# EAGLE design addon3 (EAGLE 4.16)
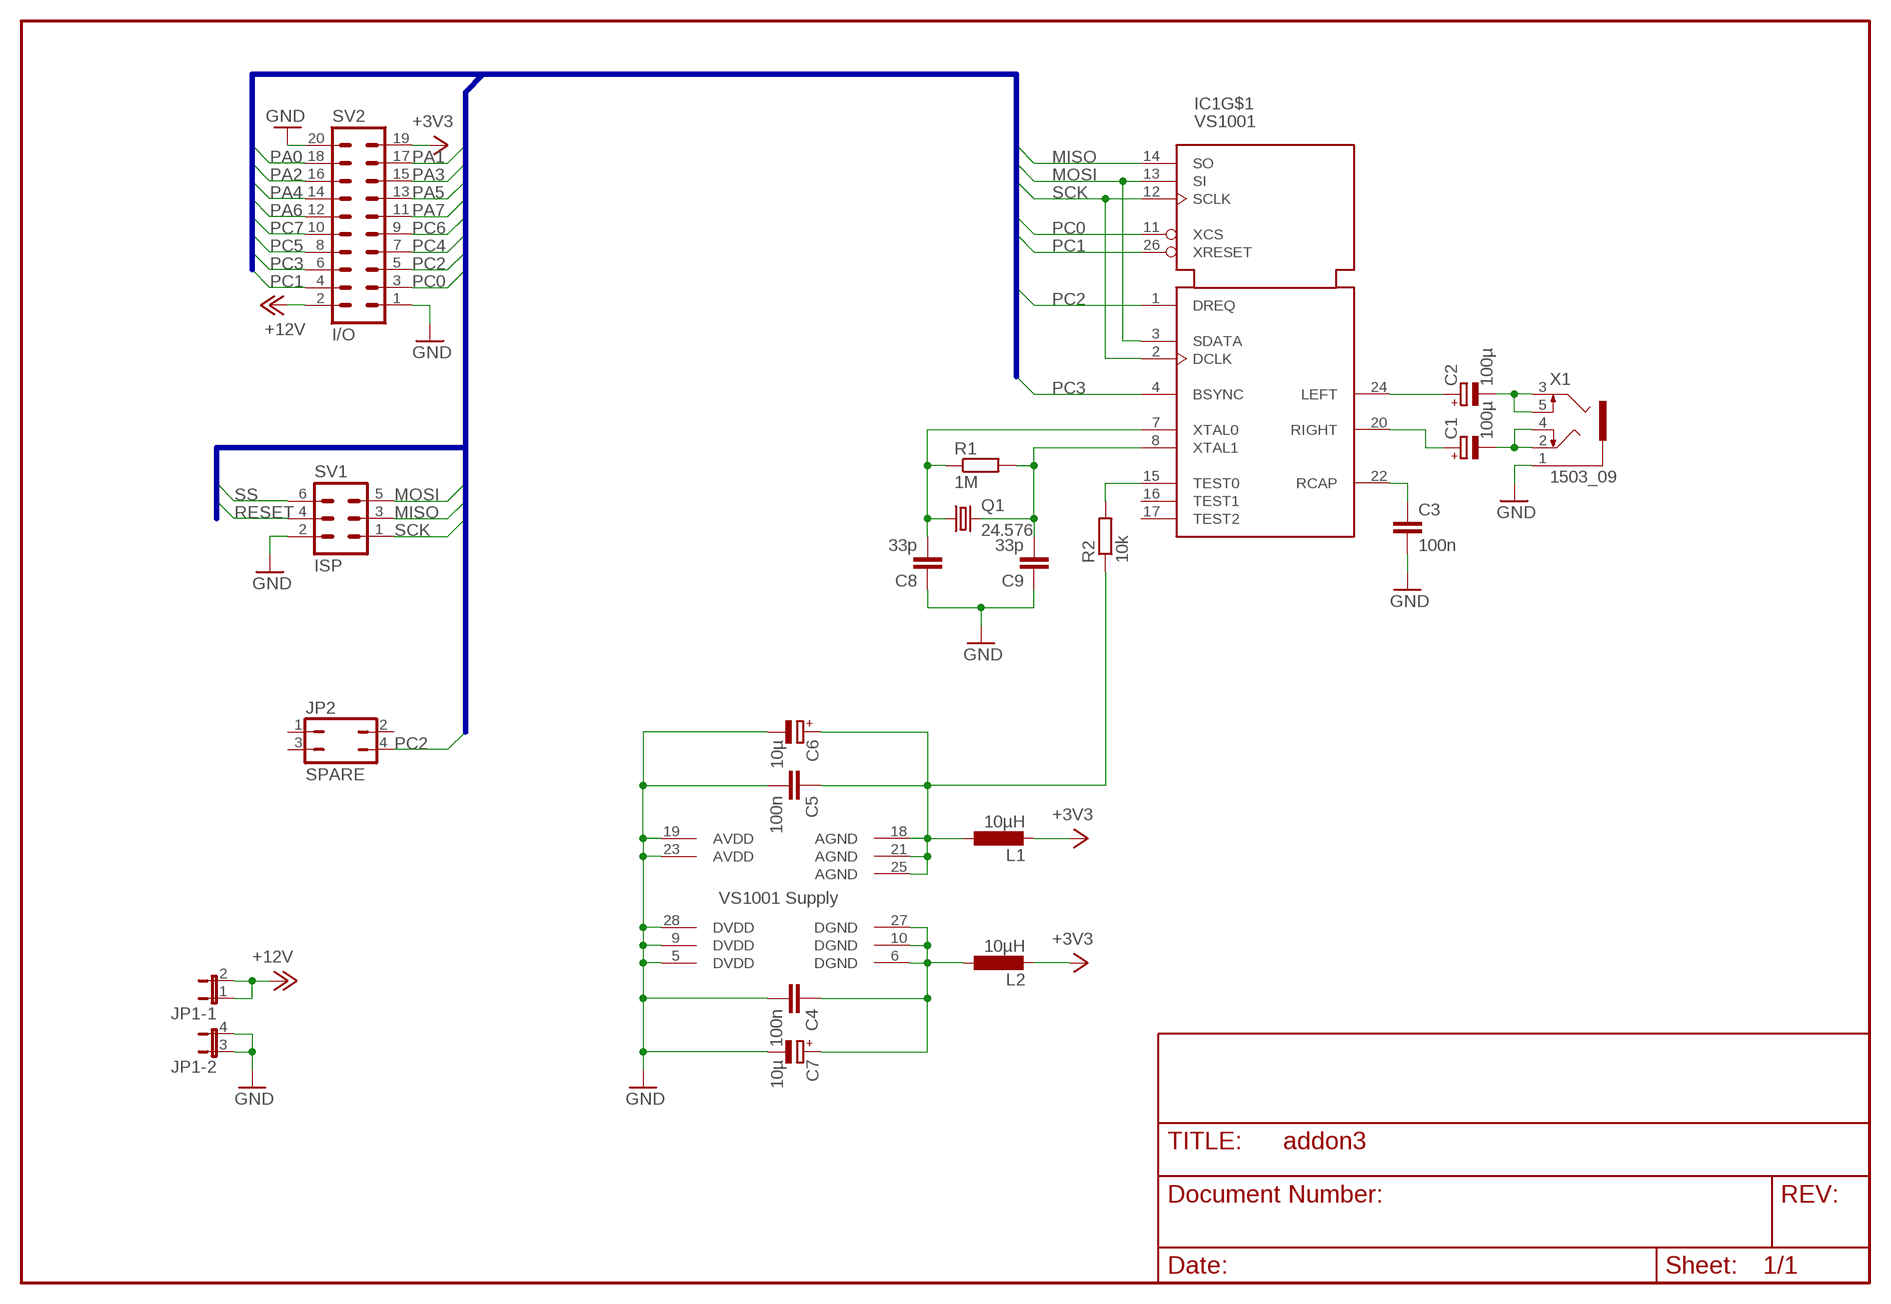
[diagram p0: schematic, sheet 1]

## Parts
C1  100µ  CPOL-EUSMCD  [SMC_D]
C2  100µ  CPOL-EUSMCD  [SMC_D]
C3  100n  C-EUC0805  [C0805]
C4  100n  C-EUC0805  [C0805]
C5  100n  C-EUC0805  [C0805]
C6  10µ  CPOL-EUSMCA  [SMC_A]
C7  10µ  CPOL-EUSMCA  [SMC_A]
C8  33p  C-EUC0603  [C0603]
C9  33p  C-EUC0603  [C0603]
IC1  VS1001-SOIC-28  [SO-28L]
JP1  JP2QE  [JP2Q]
JP2  SPARE  JP2Q  [JP2Q]
L1  10µH  L-EUL3216C  [L3216C]
L2  10µH  L-EUL3216C  [L3216C]
Q1  24.576  CRYTALHC18U-V  [HC18U-V]
R1  1M  R-EU_R0805  [R0805]
R2  10k  R-EU_R0805  [R0805]
SV1  ISP  MA03-2  [MA03-2]
SV2  I/O  MA10-2  [MA10-2]
X1  1503_09  [1503_09]

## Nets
+3V3: L1.2 L2.2 SV2.19
+12V: JP1.1 JP1.2 SV2.2
GND: C3.2 C4.2 C5.2 C6.- C7.- C8.1 C9.1 IC1.5(DVDD) IC1.9(DVDD) IC1.19(AVDD) IC1.23(AVDD) IC1.28(DVDD) JP1.3 JP1.4 SV1.2 SV2.1 SV2.20 X1.1
MISO: IC1.14(SO) SV1.3
MOSI: IC1.3(SDATA) IC1.13(SI) SV1.5
N$1: C3.1 IC1.22(RCAP)
N$2: C2.- X1.3 X1.5
N$3: C1.- X1.2 X1.4
N$4: C2.+ IC1.24(LEFT)
N$5: C1.+ IC1.20(RIGHT)
N$6: C5.1 C6.+ IC1.18(AGND) IC1.21(AGND) IC1.25(AGND) L1.1 R2.1
N$7: C4.1 C7.+ IC1.6(DGND) IC1.10(DGND) IC1.27(DGND) L2.1
N$8: C8.2 IC1.7(XTAL0) Q1.1 R1.1
N$9: C9.2 IC1.8(XTAL1) Q1.2 R1.2
N$11: IC1.15(TEST0) R2.2
PA0: SV2.18
PA1: SV2.17
PA2: SV2.16
PA3: SV2.15
PA4: SV2.14
PA5: SV2.13
PA6: SV2.12
PA7: SV2.11
PC0: IC1.11(XCS) SV2.3
PC1: IC1.26(XRESET) SV2.4
PC2: IC1.1(DREQ) JP2.4 SV2.5
PC3: IC1.4(BSYNC) SV2.6
PC4: SV2.7
PC5: SV2.8
PC6: SV2.9
PC7: SV2.10
RESET: SV1.4
SCK: IC1.2(DCLK) IC1.12(SCLK) SV1.1
SS: SV1.6
Unconnected: IC1.16(TEST1) IC1.17(TEST2) JP2.1 JP2.2 JP2.3

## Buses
PA[0..7],PC[0..7],SCK,MOSI,MISO,SS,RESET

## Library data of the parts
C1 C2 C6 C7 = rcl:CPOL-EU: POLARIZED CAPACITOR, European symbol
C3-C5 C8 C9 = rcl:C-EU: CAPACITOR, European symbol
IC1 = vs1001:VS1001: MP3 decoder chip from VLSI Solutions
JP1 = jumper:JP2QE: JUMPER
JP2 = jumper:JP2Q: JUMPER
L1 L2 = rcl:L-EU: INDUCTOR, European symbol
Q1 = crystal:CRYTAL: CRYSTAL
R1 R2 = rcl:R-EU_: RESISTOR, European symbol
SV1 = con-lstb:MA03-2: PIN HEADER
SV2 = con-lstb:MA10-2: PIN HEADER
X1 = con-lumberg:1503_09: Jack connectors according to JISC 6560, 3.5 mm Klinkeneinbaukupplung nach JISC 6560, 3,5 mm, 3-polig/ stereo, abgewinkelte Ausführung, mit 2 Öffnern und Lötaugen, für Leiterplatten Rückseitenmontage Source: http://www.lumberg.com/Produkte/PDFs/1503_09.pdf

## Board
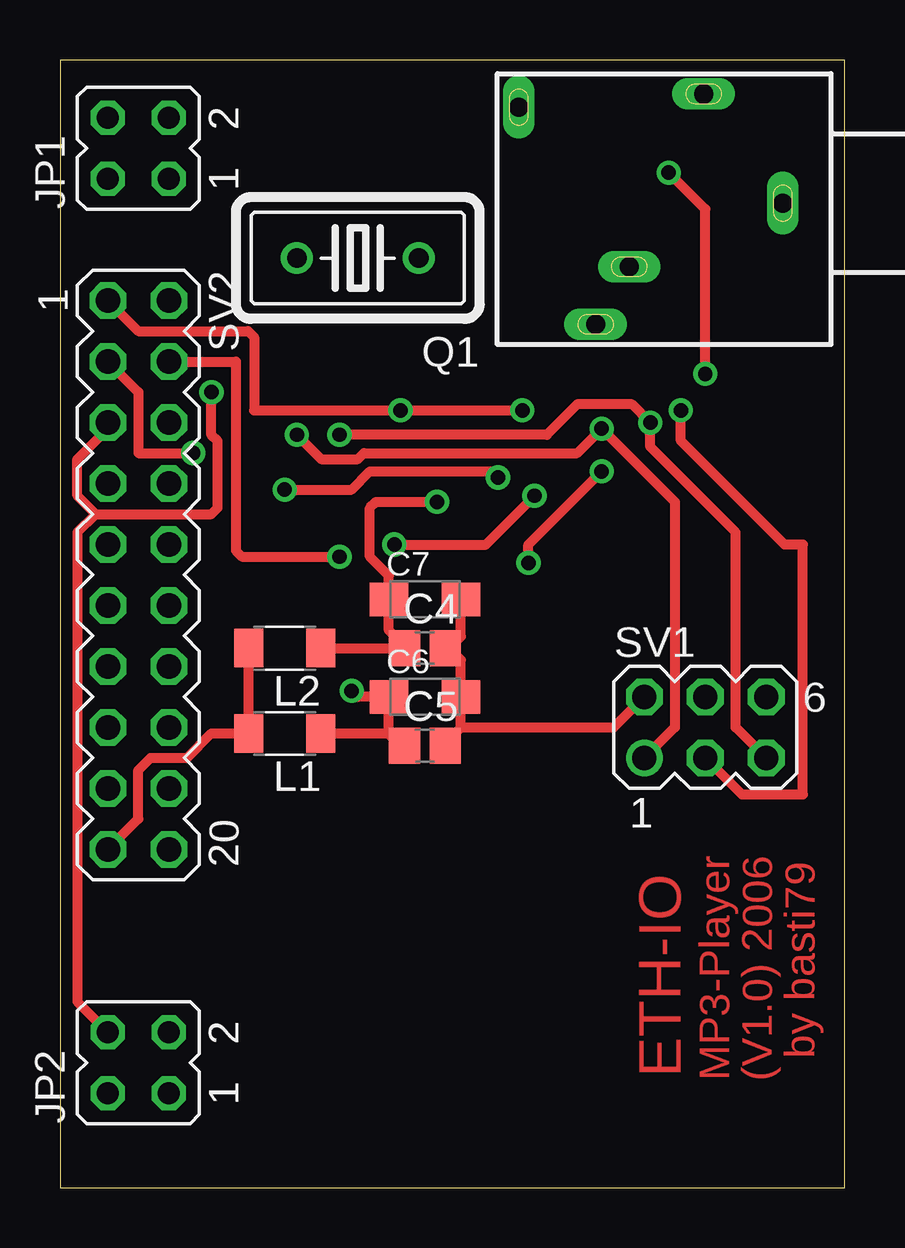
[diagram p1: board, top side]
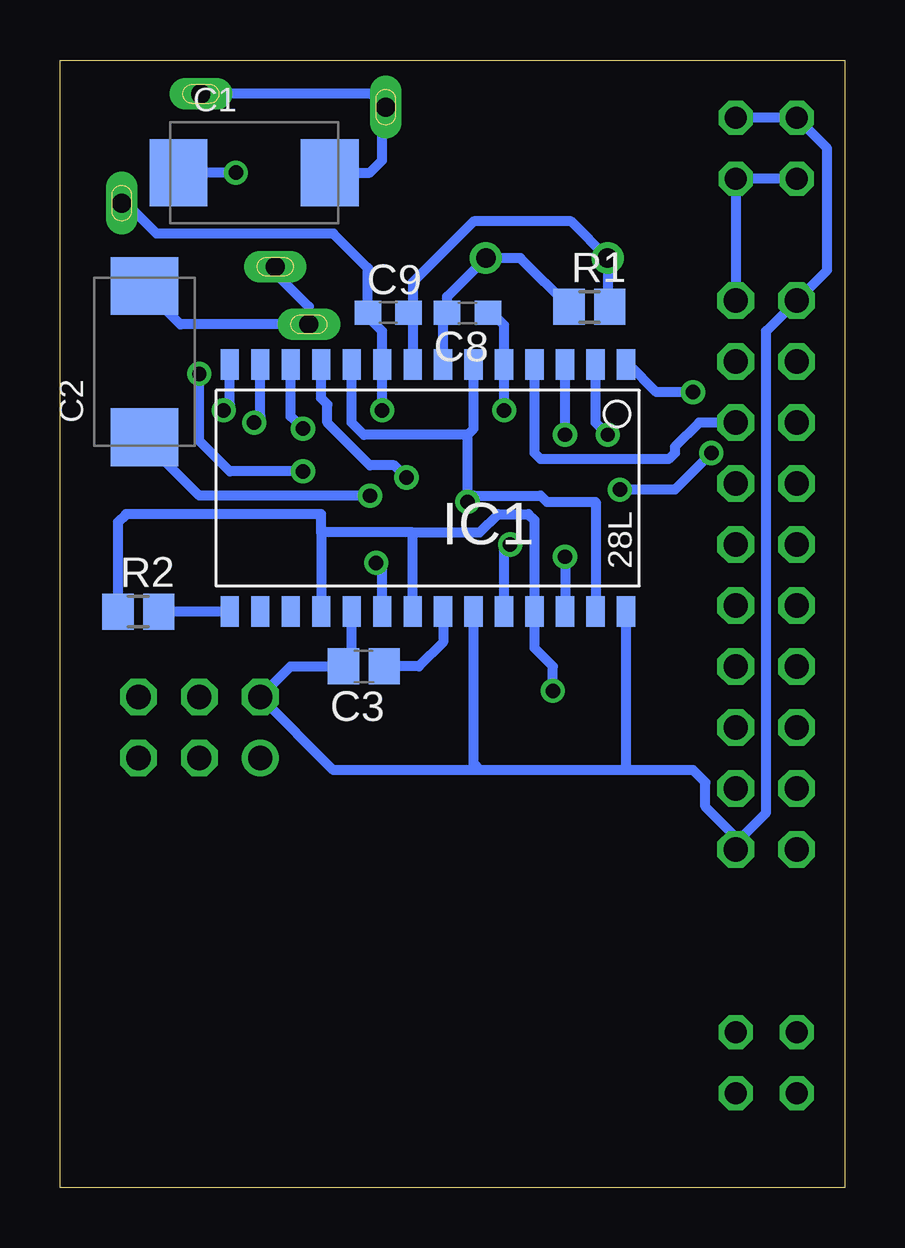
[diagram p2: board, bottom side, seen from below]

Size 32.69 x 46.98 mm. Coordinates in mm from the lower left corner, seen from the top.
Outline: 0,0 32.69,0 32.69,46.98 0,46.98 0,0
Copper layers (1*16): Top 0.035mm / dielectric 1.5mm / Bottom 0.035mm
Design rules "default": minimum track width 10mil, minimum drill 20mil, track to track 8mil, track to pad 8mil, pad to pad 8mil, via to via 8mil, smd to smd 8mil, copper to edge 20mil, drill to drill 8mil, minimum pad ring 10mil, minimum via ring 8mil, stop-mask expansion 4mil, vias tented up to drill 0mil, thermal gap 10mil
tKeepout: area 6.6,-0.1 to 23.3,16.9
bKeepout: area 6.6,-0.1 to 23.3,16.9; area 0,39.7 to 6.8,47.1; area 22.6,16.1 to 31.2,22.2

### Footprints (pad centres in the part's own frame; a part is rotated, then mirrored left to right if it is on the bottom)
SMC_D = smd 2.4 x 2.8: + -3.15,0; - 3.15,0
C0805 = smd 1.3 x 1.5: 1 -0.85,0; 2 0.85,0
SMC_A = smd 1.6 x 1.4: + -1.5,0; - 1.5,0
C0603 = smd 1.1 x 1: 1 -0.85,0; 2 0.85,0
SO-28L = smd 0.762 x 1.27: 1 -7.62,-5.207; 2 -6.35,-5.207; 3 -5.08,-5.207; 4 -3.81,-5.207; 5 -2.54,-5.207; 6 -1.27,-5.207; 7 0,-5.207; 8 1.27,-5.207; 9 2.54,-5.207; 10 3.81,-5.207; 11 5.08,-5.207; 12 6.35,-5.207; 13 7.62,-5.207; 14 8.89,-5.207; 15 8.89,5.08; 16 7.62,5.08; 17 6.35,5.08; 18 5.08,5.08; 19 3.81,5.08; 20 2.54,5.08; 21 1.27,5.08; 22 0,5.08; 23 -1.27,5.08; 24 -2.54,5.08; 25 -3.81,5.08; 26 -5.08,5.08; 27 -6.35,5.08; 28 -7.62,5.08
JP2Q = drill 0.914 octagon: 1 -1.27,-1.27; 2 -1.27,1.27; 3 1.27,-1.27; 4 1.27,1.27
L3216C = smd 1.2 x 1.6: 1 -1.5,0; 2 1.5,0
HC18U-V = drill 0.813 round: 1 -2.54,0; 2 2.54,0
R0805 = smd 1.3 x 1.5: 1 -0.85,0; 2 0.85,0
MA03-2 = drill 1.016 round: 1 -2.54,-1.27 | drill 1.016 octagon: 2 -2.54,1.27; 3 0,-1.27; 4 0,1.27; 5 2.54,-1.27; 6 2.54,1.27
MA10-2 = drill 1.016 octagon: 1 -11.43,-1.27; 2 -11.43,1.27; 3 -8.89,-1.27; 4 -8.89,1.27; 5 -6.35,-1.27; 6 -6.35,1.27; 7 -3.81,-1.27; 8 -3.81,1.27; 9 -1.27,-1.27; 10 -1.27,1.27; 11 1.27,-1.27; 12 1.27,1.27; 13 3.81,-1.27; 14 3.81,1.27; 15 6.35,-1.27; 16 6.35,1.27; 17 8.89,-1.27; 18 8.89,1.27; 19 11.43,-1.27; 20 11.43,1.27
1503_09 = drill 0.8 pad 1.2 long: 1 0,-2.1; 2 -4.55,-5.4; 3 5.05,-9.9; 4 -4,-13.1; 5 2.65,-8.5

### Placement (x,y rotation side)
C1  24.6,42.29 0 bottom
C2  29.17,34.41 90 bottom
C3  20.03,21.71 180 bottom
C4  15.2,22.47 0 top
C5  15.2,18.41 0 top
C6  15.2,20.44 0 top
C7  15.2,24.51 0 top
C8  15.71,36.44 180 bottom
C9  19.01,36.44 0 bottom
IC1  16.73,29.08 180 bottom
JP1  3.26,43.3 90 top
JP2  3.26,5.2 90 top
L1  9.36,18.92 180 top
L2  9.36,22.47 180 top
Q1  12.41,38.73 180 top
R1  10.63,36.7 0 bottom
R2  29.43,24 0 bottom
SV1  26.89,19.17 0 top
SV2  3.26,25.52 270 top
X1  32.22,41.02 270 top

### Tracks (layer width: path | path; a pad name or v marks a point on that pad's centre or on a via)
+3V3
  Top 0.406: L2.2 7.84,22.47 7.86,22.45 L1.2 | SV2.19 3.26,15.36 3.26,17.39 3.77,17.9 5.3,17.9 6.31,18.92 L1.2 | 8.09,18.92 L1.2
+12V
  Bottom 0.406: JP1.2 JP1.1 SV2.2
GND  (via drill 0.6)
  Top 0.406: C5.2 15.96,18.41 16.7,19.15 | 16.7,19.15 C6.- 16.7,21.99 16.22,22.47 | 16.22,22.47 C4.2 | C7.- 16.7,22.96 16.22,22.47 | 16.7,19.15 23.05,19.15 SV1.2 | v19.27,32.38 v14.19,32.38 8.09,32.38 8.09,35.43 7.84,35.68 3.26,35.68 SV2.1
  Bottom 0.406: 9.11,17.39 6.31,17.39 5.8,16.89 5.8,15.87 4.53,14.6 SV2.20 4.53,14.35 3.26,15.62 3.26,35.68 SV2.1 0.72,38.22 0.72,43.3 JP1.4 JP1.3 | 9.11,17.39 15.2,17.39 | 15.2,17.39 21.3,17.39 SV1.2 23.08,21.71 21.04,21.71 | C8.1 14.69,36.44 14.19,35.94 IC1.5 v14.19,32.38 | X1.1 29.93,41.02 28.66,39.75 21.3,39.75 19.86,38.31 C9.1 20.03,36.44 19.27,35.68 IC1.9 v19.27,32.38 | 9.11,17.39 IC1.28 | 21.04,21.71 C3.2 | IC1.19 20.54,22.22 21.04,21.71 | IC1.23 15.46,17.65 15.2,17.39
MISO  (via drill 0.6)
  Top 0.406: SV1.3 28.41,16.38 30.95,16.38 30.95,26.79 30.19,26.79 25.87,31.11 v25.87,32.38 25.87,32.63
  Bottom 0.406: IC1.14 25.62,32.63 v25.87,32.38
MOSI  (via drill 0.6)
  Top 0.406: SV1.5 28.16,19.17 28.16,27.3 24.6,30.86 v24.6,31.87 23.84,32.63 21.55,32.63 20.28,31.36 v11.65,31.36
  Bottom 0.406: v24.6,31.87 24.35,32.13 IC1.13 | v11.65,31.36 IC1.3
N$1
  Bottom 0.406: IC1.22 16.73,22.73 17.74,21.71 C3.1
N$2
  Bottom 0.406: X1.5 23.72,38.34 23.84,38.22 22.32,36.7 X1.3 27.68,35.97 29.17,37.46 C2.-
N$3
  Bottom 0.406: X1.2 19.75,45.57 arc90 19.27,45.08 arc-90 19.2,45.02 X1.4 19.12,44.93 19.01,44.83 19.27,44.57 19.27,42.79 19.77,42.29 C1.-
N$4  (via drill 0.6)
  Top 0.406: v13.93,26.79 17.74,26.79 v19.77,28.82
  Bottom 0.406: IC1.24 14.19,26.54 v13.93,26.79 | 28.41,30.6 29.17,31.36 C2.+ 29.17,31.11 26.89,28.82 v19.77,28.82
N$5  (via drill 0.6)
  Top 0.406: v19.52,26.03 19.52,26.79 v22.57,29.84 | v26.89,33.9 26.89,40.76 v25.36,42.29
  Bottom 0.406: 27.9,42.29 C1.+ v25.36,42.29 | IC1.20 19.27,25.78 v19.52,26.03 | v22.57,29.84 25.62,29.84 26.89,31.11 v26.89,33.9
N$6  (via drill 0.6)
  Top 0.406: L1.1 13.93,18.92 14.44,18.41 C5.1 14.19,18.41 13.7,18.89 C6.+ 12.41,20.44 v12.15,20.7
  Bottom 0.406: v12.15,20.7 12.15,21.71 12.92,22.47 IC1.25 12.92,27.81 13.17,28.06 14.44,28.06 15.2,27.3 18,27.3 | R2.1 30.28,27.72 29.93,28.06 21.81,28.06 21.81,27.3 | 21.81,27.3 IC1.18 | IC1.21 18,27.3 | 18,27.3 21.81,27.3
N$7  (via drill 0.6)
  Top 0.406: L2.1 C4.1 14.44,22.47 13.7,23.21 C7.+ 13.7,25.5 12.92,26.28 12.92,28.32 13.17,28.57 v15.71,28.57
  Bottom 0.406: 15.46,34.41 IC1.6 15.46,31.62 15.71,31.36 | 15.71,31.36 20.03,31.36 20.54,31.87 IC1.10 | 15.71,31.36 v15.71,28.57 15.46,28.82 12.66,28.82 12.41,28.57 10.38,28.57 IC1.27
N$8
  Bottom 0.406: IC1.7 16.73,36.19 16.47,36.44 C8.2 16.56,37.12 Q1.1 13.51,38.73 R1.1
N$9
  Bottom 0.406: IC1.8 18,36.19 18.25,36.44 C9.2 18,36.44 18,37.71 15.46,40.25 11.39,40.25 Q1.2 9.87,36.7 R1.2
N$11
  Bottom 0.406: 28.66,24 R2.2 IC1.15
PC0  (via drill 0.6)
  Top 0.406: SV2.3 3.26,33.14 3.26,30.6 v5.55,30.6 | v9.36,29.08 12.15,29.08 12.92,29.84 18,29.84 v18.25,29.59
  Bottom 0.406: IC1.11 21.81,32.89 21.55,32.63 21.55,31.87 19.77,30.09 18.76,30.09 v18.25,29.59 | v5.55,30.6 7.07,29.08 v9.36,29.08
PC1  (via drill 0.6)
  Top 0.406: SV2.4 7.33,34.41 7.33,26.54 7.58,26.28 v11.65,26.28
  Bottom 0.406: v11.65,26.28 IC1.26
PC2  (via drill 0.6)
  Top 0.406: v6.31,33.14 6.31,31.36 6.57,31.11 6.57,28.32 6.31,28.06 1.49,28.06 | SV2.5 1.99,31.62 0.72,30.35 0.72,28.82 1.49,28.06 | 1.49,28.06 0.72,27.3 0.72,7.74 JP2.4
  Bottom 0.406: IC1.1 8.98,34.28 7.84,33.14 v6.31,33.14
PC3
  Bottom 0.406: SV2.6 6.06,31.87 7.07,30.86 7.07,30.6 7.33,30.35 12.66,30.35 12.92,30.6 IC1.4
SCK  (via drill 0.6)
  Top 0.406: SV1.1 25.62,19.17 25.62,28.57 v22.57,31.62 21.55,30.6 12.66,30.6 12.41,30.35 10.88,30.35 v9.87,31.36
  Bottom 0.406: v22.57,31.62 23.08,32.13 IC1.12 | IC1.2 10.38,31.87 v9.87,31.36

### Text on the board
Top: MP3-Player | (V1.0) 2006 | ETH-IO | by basti79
